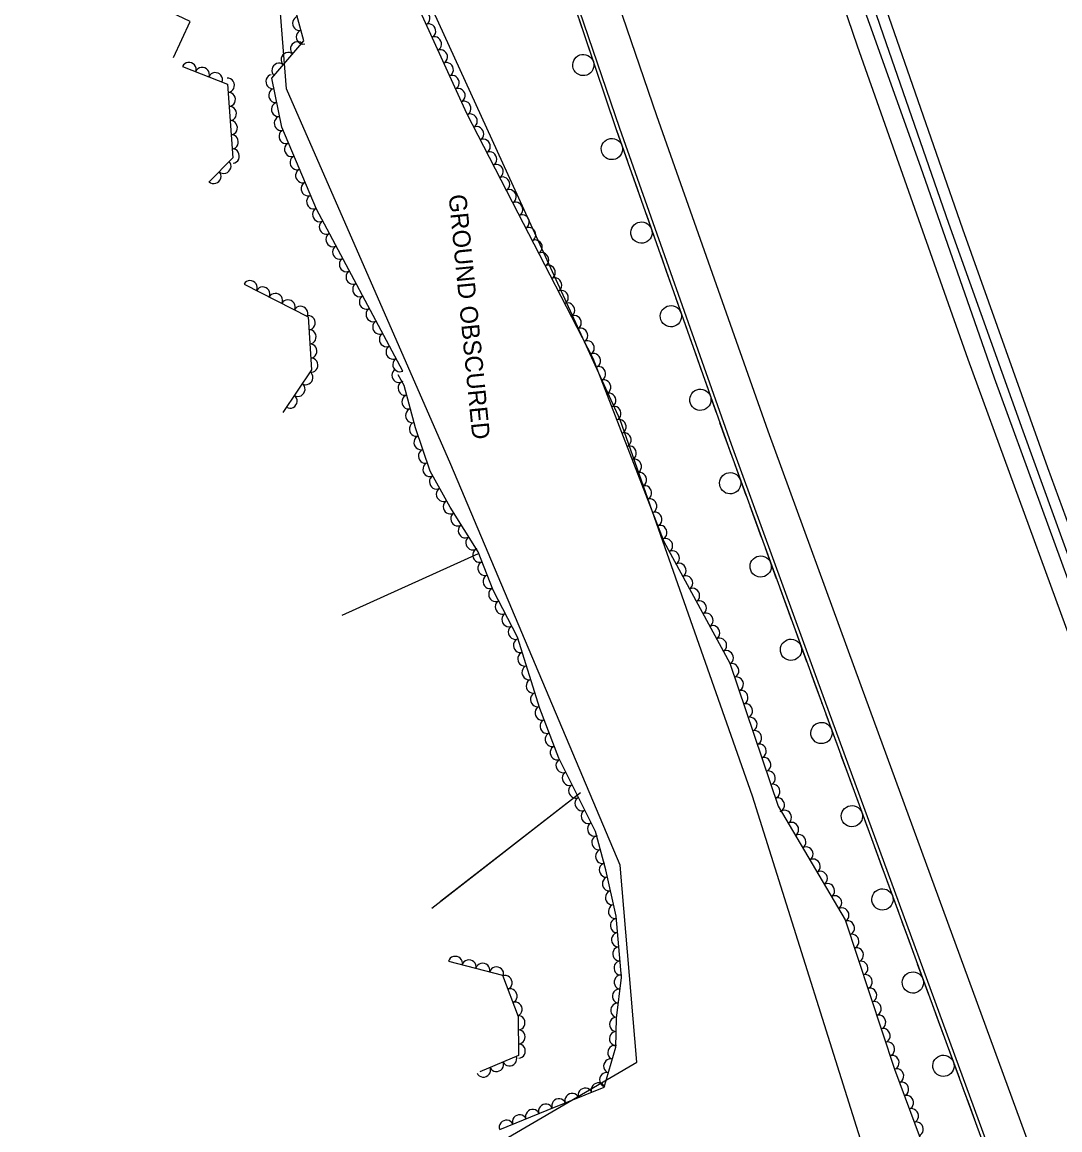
# Model space of a CAD drawing. Extents: x 1746719 to 1766531, y 631721 to 662391.
# Drawn here: x 1754164.2 to 1754457, y 649456.3 to 649768.8 of the extents above; entities that cross this region are included whole.
import ezdxf

# ---------------------------------------------------------------- set-up
doc = ezdxf.new("R2010")
doc.units = 0
for name, color, linetype in [('SURVEY - AERIAL SURVEY - Photo Control - Points - Elevations', 7, 'Continuous'), ('SURVEY - AERIAL SURVEY - Photo Control - Points - Locators', 7, 'Continuous'), ('SURVEY - AERIAL SURVEY - Photo Control - Points - Numbers', 7, 'Continuous'), ('SURVEY - AERIAL SURVEY - Photo Control with Text', 7, 'Continuous'), ('SURVEY - CENTERLINE - Existing Roads Curve Text', 7, 'Continuous')]:
    doc.layers.add(name, color=color, linetype=linetype)

msp = doc.modelspace()

# ---------------------------------------------------------------- linework, layer by layer
at = {"layer": 'SURVEY - AERIAL SURVEY - Photo Control - Points - Elevations'}
for points in [[(1754298.66, 649872.79), (1754343.18, 649742.47), (1754374.58, 649653.49), (1754400.82, 649581.61), (1754453.23, 649438.62)], [(1754289.89, 649864.41), (1754332.79, 649738.86), (1754364.23, 649649.77), (1754390.49, 649577.83), (1754442.91, 649434.83)], [(1754372.91, 649841.05), (1754399.86, 649762.15), (1754431.05, 649673.76), (1754457.17, 649602.22), (1754509.57, 649459.27)], [(1754519.88, 649459.84), (1754496.93, 649522.97), (1754475.36, 649583.78), (1754453.6, 649643.04), (1754429.6, 649710.4), (1754402.92, 649787.27), (1754386.52, 649835.23)]]:
    msp.add_lwpolyline(points, dxfattribs=at)
at = {"layer": 'SURVEY - AERIAL SURVEY - Photo Control - Points - Locators'}
msp.add_lwpolyline([(1754306.65, 649427.15), (1754301.44, 649454.25), (1754337.64, 649475.34), (1754332.91, 649530.99), (1754285.2, 649644.02), (1754238.76, 649749.99), (1754236.2, 649783.3), (1754205.23, 649865.29), (1754178.89, 649843.08), (1754164.2, 649889.48), (1754197.11, 649948.37), (1754220.8, 649913.17), (1754277.14, 649778.61), (1754332.9, 649656.66), (1754370.16, 649550.51), (1754404.93, 649440.26), (1754306.65, 649427.15)], dxfattribs=at)
at = {"layer": 'SURVEY - AERIAL SURVEY - Photo Control - Points - Numbers'}
for points in [[(1754289.46, 649864.22), (1754331.85, 649738.54), (1754363.29, 649649.43), (1754389.55, 649577.48), (1754441.97, 649434.49)], [(1754379.58, 649838.2), (1754396.39, 649787.83), (1754417.71, 649728.02), (1754438.48, 649668.45), (1754465.02, 649595.86), (1754484.29, 649542.97), (1754514.24, 649459.31)], [(1754516.62, 649459.65), (1754501.04, 649503.67), (1754483.8, 649551.83), (1754466.56, 649598.63), (1754446.68, 649653.43), (1754425.68, 649712.01), (1754407.27, 649765.12), (1754389.44, 649816.85), (1754382.87, 649836.79)], [(1754321.42, 649769.46), (1754322.92, 649765.01)], [(1754323.94, 649761.98), (1754326.88, 649753.26)], [(1754327.9, 649750.23), (1754329.41, 649745.77)], [(1754329.41, 649745.77), (1754330.91, 649741.32)], [(1754331.93, 649738.29), (1754335, 649729.61)], [(1754336.06, 649726.59), (1754337.62, 649722.16)], [(1754337.62, 649722.16), (1754339.19, 649717.73)], [(1754340.25, 649714.71), (1754343.31, 649706.04)], [(1754344.38, 649703.02), (1754345.94, 649698.59)], [(1754345.94, 649698.59), (1754347.51, 649694.16)], [(1754348.57, 649691.14), (1754351.63, 649682.46)], [(1754352.7, 649679.44), (1754354.26, 649675.01)], [(1754354.26, 649675.01), (1754355.82, 649670.58)], [(1754356.89, 649667.56), (1754359.95, 649658.89)], [(1754361.02, 649655.87), (1754362.58, 649651.44)], [(1754362.58, 649651.44), (1754363.29, 649649.43), (1754364.17, 649647.01)], [(1754365.27, 649644.01), (1754368.42, 649635.37)], [(1754369.52, 649632.36), (1754371.13, 649627.95)], [(1754371.13, 649627.95), (1754372.74, 649623.53)], [(1754373.84, 649620.52), (1754377, 649611.88)], [(1754378.09, 649608.88), (1754379.71, 649604.46)], [(1754379.71, 649604.46), (1754381.32, 649600.05)], [(1754382.42, 649597.04), (1754385.57, 649588.4)], [(1754386.67, 649585.39), (1754388.28, 649580.98)], [(1754388.28, 649580.98), (1754389.55, 649577.48), (1754389.89, 649576.56)], [(1754390.99, 649573.56), (1754394.16, 649564.92)], [(1754395.26, 649561.92), (1754396.88, 649557.5)], [(1754396.88, 649557.5), (1754398.5, 649553.09)], [(1754399.6, 649550.08), (1754402.76, 649541.45)], [(1754403.86, 649538.44), (1754405.48, 649534.03)], [(1754405.48, 649534.03), (1754407.1, 649529.62)], [(1754408.2, 649526.61), (1754411.37, 649517.97)], [(1754412.47, 649514.97), (1754414.09, 649510.56)], [(1754414.09, 649510.56), (1754415.7, 649506.14)], [(1754416.8, 649503.14), (1754419.97, 649494.5)], [(1754421.07, 649491.5), (1754422.69, 649487.08)], [(1754422.69, 649487.08), (1754424.31, 649482.67)], [(1754425.41, 649479.67), (1754428.57, 649471.03)], [(1754429.68, 649468.02), (1754431.29, 649463.61)], [(1754431.29, 649463.61), (1754432.91, 649459.2)]]:
    msp.add_lwpolyline(points, dxfattribs=at)
for centre, start, end in [((1754322.55, 649756.7), 131.9077, 131.8937), ((1754330.62, 649733), 132.7034, 132.6894), ((1754338.94, 649709.42), 132.7034, 132.6894), ((1754347.26, 649685.84), 132.7034, 132.6894), ((1754355.58, 649662.27), 132.7034, 132.6894), ((1754364.01, 649638.7), 133.3255, 133.3115), ((1754372.59, 649615.22), 133.3255, 133.3115), ((1754381.16, 649591.73), 133.3255, 133.3115), ((1754389.74, 649568.25), 133.3982, 133.3842), ((1754398.35, 649544.78), 133.3982, 133.3842), ((1754406.95, 649521.3), 133.3982, 133.3842), ((1754415.56, 649497.83), 133.3982, 133.3842), ((1754424.16, 649474.36), 133.3982, 133.3842)]:
    msp.add_arc(centre, 3, start, end, dxfattribs=at)
at = {"layer": 'SURVEY - AERIAL SURVEY - Photo Control with Text'}
for points in [[(1754166.74, 649890.48), (1754176.87, 649920.51), (1754184.32, 649931.68), (1754190.2, 649940.32), (1754197.86, 649945.85), (1754217.64, 649930.63), (1754230.89, 649883.58), (1754250.56, 649822.66), (1754267.73, 649791.06), (1754289.59, 649743.11), (1754304.09, 649714.97), (1754325.28, 649673.97), (1754345.25, 649622.29), (1754363.86, 649587.9), (1754377.55, 649547.63), (1754396.42, 649515.54), (1754410.38, 649473.41), (1754419.07, 649449.85)], [(1754271.62, 649670.36), (1754247.23, 649716.04), (1754237.44, 649739.16), (1754234.66, 649753.04), (1754243.71, 649763.54), (1754236.47, 649790.24), (1754224.48, 649823.51), (1754211.15, 649858.52), (1754204.97, 649870.03), (1754198.07, 649874.53), (1754190, 649863.67), (1754179.33, 649845.57)], [(1754209.47, 649756.3), (1754222.19, 649751.34), (1754223.64, 649730.51), (1754216.86, 649723.64)], [(1754226.81, 649694.9), (1754244.89, 649685.69), (1754245.85, 649670.72), (1754237.79, 649658.7)], [(1754298.95, 649456.36), (1754312.36, 649461.84), (1754328.4, 649468.32), (1754331.77, 649479.58), (1754331.87, 649487.77), (1754333.31, 649499.29), (1754331.81, 649516.59), (1754328.92, 649529.61), (1754325.95, 649540.49), (1754315.67, 649561.15), (1754310.32, 649575.14), (1754303.98, 649595.32), (1754297.09, 649608.55), (1754292.85, 649619.39), (1754284.95, 649631.96), (1754279.35, 649642.09), (1754275.23, 649654.34), (1754271.97, 649666.27), (1754270.33, 649669.26)], [(1754284.51, 649503.83), (1754299.76, 649499.96), (1754304.19, 649488.27), (1754304.3, 649477.24), (1754293.35, 649472.61)]]:
    msp.add_lwpolyline(points, dxfattribs=at)
for centre, major_axis in [((1754277.34, 649769.98), (0.83, -1.82)), ((1754242.38, 649768.45), (-0.52, 1.93)), ((1754279, 649766.34), (0.83, -1.82)), ((1754243.42, 649764.59), (-0.52, 1.93)), ((1754280.66, 649762.7), (0.83, -1.82)), ((1754241.82, 649761.34), (1.31, 1.51)), ((1754282.32, 649759.06), (0.83, -1.82)), ((1754239.2, 649758.31), (1.31, 1.51)), ((1754211.33, 649755.57), (1.86, -0.73)), ((1754215.06, 649754.12), (1.86, -0.73)), ((1754236.59, 649755.28), (1.31, 1.51)), ((1754283.98, 649755.43), (0.83, -1.82)), ((1754218.78, 649752.67), (1.86, -0.73)), ((1754222.21, 649750.99), (0.14, -2)), ((1754234.87, 649752.02), (-0.39, 1.96)), ((1754285.64, 649751.79), (0.83, -1.82)), ((1754222.49, 649747), (0.14, -2)), ((1754235.65, 649748.1), (-0.39, 1.96)), ((1754287.3, 649748.15), (0.83, -1.82)), ((1754236.44, 649744.17), (-0.39, 1.96)), ((1754288.95, 649744.51), (0.83, -1.82)), ((1754222.77, 649743.01), (0.14, -2)), ((1754290.72, 649740.92), (0.92, -1.78)), ((1754223.04, 649739.02), (0.14, -2)), ((1754237.22, 649740.25), (-0.39, 1.96)), ((1754292.55, 649737.36), (0.92, -1.78)), ((1754223.32, 649735.03), (0.14, -2)), ((1754238.57, 649736.5), (-0.78, 1.84)), ((1754223.6, 649731.04), (0.14, -2)), ((1754240.13, 649732.82), (-0.78, 1.84)), ((1754294.39, 649733.81), (0.92, -1.78)), ((1754241.69, 649729.13), (-0.78, 1.84)), ((1754296.22, 649730.25), (0.92, -1.78)), ((1754221.2, 649728.04), (-1.4, -1.42)), ((1754243.25, 649725.45), (-0.78, 1.84)), ((1754298.05, 649726.7), (0.92, -1.78)), ((1754218.39, 649725.2), (-1.4, -1.42)), ((1754299.88, 649723.14), (0.92, -1.78)), ((1754244.81, 649721.77), (-0.78, 1.84)), ((1754301.71, 649719.58), (0.92, -1.78)), ((1754246.37, 649718.08), (-0.78, 1.84)), ((1754303.55, 649716.03), (0.92, -1.78)), ((1754248.07, 649714.47), (-0.94, 1.76)), ((1754305.38, 649712.47), (0.92, -1.78)), ((1754249.95, 649710.94), (-0.94, 1.76)), ((1754251.84, 649707.41), (-0.94, 1.76)), ((1754307.22, 649708.92), (0.92, -1.78)), ((1754253.72, 649703.88), (-0.94, 1.76)), ((1754309.05, 649705.37), (0.92, -1.78)), ((1754255.61, 649700.36), (-0.94, 1.76)), ((1754310.89, 649701.81), (0.92, -1.78)), ((1754312.73, 649698.26), (0.92, -1.78)), ((1754228.59, 649693.99), (1.78, -0.91)), ((1754257.49, 649696.83), (-0.94, 1.76)), ((1754314.56, 649694.71), (0.92, -1.78)), ((1754232.16, 649692.18), (1.78, -0.91)), ((1754235.72, 649690.36), (1.78, -0.91)), ((1754259.37, 649693.3), (-0.94, 1.76)), ((1754316.4, 649691.15), (0.92, -1.78)), ((1754239.29, 649688.55), (1.78, -0.91)), ((1754261.26, 649689.77), (-0.94, 1.76)), ((1754318.23, 649687.6), (0.92, -1.78)), ((1754242.85, 649686.73), (1.78, -0.91)), ((1754263.14, 649686.24), (-0.94, 1.76)), ((1754320.07, 649684.04), (0.92, -1.78)), ((1754245, 649683.99), (0.13, -2)), ((1754265.03, 649682.71), (-0.94, 1.76)), ((1754245.26, 649680), (0.13, -2)), ((1754266.91, 649679.18), (-0.94, 1.76)), ((1754321.91, 649680.49), (0.92, -1.78)), ((1754245.51, 649676), (0.13, -2)), ((1754268.79, 649675.66), (-0.94, 1.76)), ((1754323.74, 649676.94), (0.92, -1.78)), ((1754245.76, 649672.01), (0.13, -2)), ((1754270.68, 649672.13), (-0.94, 1.76)), ((1754325.51, 649673.35), (0.72, -1.87)), ((1754270.43, 649669.08), (-0.96, 1.75)), ((1754326.95, 649669.62), (0.72, -1.87)), ((1754244.34, 649668.47), (-1.11, -1.66)), ((1754328.4, 649665.89), (0.72, -1.87)), ((1754242.11, 649665.15), (-1.11, -1.66)), ((1754272.17, 649665.51), (-0.53, 1.93)), ((1754329.84, 649662.16), (0.72, -1.87)), ((1754239.89, 649661.83), (-1.11, -1.66)), ((1754273.23, 649661.65), (-0.53, 1.93)), ((1754274.28, 649657.79), (-0.53, 1.93)), ((1754331.28, 649658.43), (0.72, -1.87)), ((1754275.36, 649653.94), (-0.64, 1.9)), ((1754332.72, 649654.7), (0.72, -1.87)), ((1754276.64, 649650.15), (-0.64, 1.9)), ((1754334.16, 649650.97), (0.72, -1.87)), ((1754335.61, 649647.24), (0.72, -1.87)), ((1754277.92, 649646.36), (-0.64, 1.9)), ((1754337.05, 649643.51), (0.72, -1.87)), ((1754279.19, 649642.57), (-0.64, 1.9)), ((1754281.04, 649639.03), (-0.97, 1.75)), ((1754338.49, 649639.77), (0.72, -1.87)), ((1754282.98, 649635.53), (-0.97, 1.75)), ((1754339.93, 649636.04), (0.72, -1.87)), ((1754284.91, 649632.02), (-0.97, 1.75)), ((1754341.37, 649632.31), (0.72, -1.87)), ((1754287.03, 649628.63), (-1.06, 1.69)), ((1754342.82, 649628.58), (0.72, -1.87)), ((1754289.16, 649625.25), (-1.06, 1.69)), ((1754344.26, 649624.85), (0.72, -1.87)), ((1754291.29, 649621.86), (-1.06, 1.69)), ((1754345.84, 649621.19), (0.95, -1.76)), ((1754293.24, 649618.38), (-0.73, 1.86)), ((1754347.75, 649617.67), (0.95, -1.76)), ((1754294.7, 649614.66), (-0.73, 1.86)), ((1754349.65, 649614.15), (0.95, -1.76)), ((1754296.16, 649610.94), (-0.73, 1.86)), ((1754351.56, 649610.63), (0.95, -1.76)), ((1754297.75, 649607.27), (-0.92, 1.77)), ((1754353.46, 649607.11), (0.95, -1.76)), ((1754299.6, 649603.73), (-0.92, 1.77)), ((1754355.36, 649603.6), (0.95, -1.76)), ((1754301.45, 649600.18), (-0.92, 1.77)), ((1754357.27, 649600.08), (0.95, -1.76)), ((1754359.17, 649596.56), (0.95, -1.76)), ((1754303.29, 649596.63), (-0.92, 1.77)), ((1754304.73, 649592.91), (-0.6, 1.91)), ((1754361.07, 649593.04), (0.95, -1.76)), ((1754305.93, 649589.1), (-0.6, 1.91)), ((1754362.98, 649589.53), (0.95, -1.76)), ((1754307.13, 649585.28), (-0.6, 1.91)), ((1754364.55, 649585.86), (0.64, -1.89)), ((1754308.33, 649581.47), (-0.6, 1.91)), ((1754365.84, 649582.08), (0.64, -1.89)), ((1754367.13, 649578.29), (0.64, -1.89)), ((1754309.53, 649577.65), (-0.6, 1.91)), ((1754310.81, 649573.86), (-0.71, 1.87)), ((1754368.41, 649574.5), (0.64, -1.89)), ((1754312.24, 649570.12), (-0.71, 1.87)), ((1754369.7, 649570.71), (0.64, -1.89)), ((1754313.67, 649566.39), (-0.71, 1.87)), ((1754370.99, 649566.93), (0.64, -1.89)), ((1754315.1, 649562.65), (-0.71, 1.87)), ((1754372.28, 649563.14), (0.64, -1.89)), ((1754373.56, 649559.35), (0.64, -1.89)), ((1754316.74, 649559.01), (-0.89, 1.79)), ((1754318.52, 649555.43), (-0.89, 1.79)), ((1754374.85, 649555.57), (0.64, -1.89)), ((1754320.3, 649551.85), (-0.89, 1.79)), ((1754376.14, 649551.78), (0.64, -1.89)), ((1754322.08, 649548.26), (-0.89, 1.79)), ((1754377.43, 649547.99), (0.64, -1.89)), ((1754323.86, 649544.68), (-0.89, 1.79)), ((1754379.39, 649544.51), (1.01, -1.72)), ((1754325.64, 649541.1), (-0.89, 1.79)), ((1754381.41, 649541.06), (1.01, -1.72)), ((1754383.44, 649537.62), (1.01, -1.72)), ((1754326.82, 649537.29), (-0.53, 1.93)), ((1754385.47, 649534.17), (1.01, -1.72)), ((1754327.88, 649533.43), (-0.53, 1.93)), ((1754328.93, 649529.57), (-0.43, 1.95)), ((1754387.5, 649530.72), (1.01, -1.72)), ((1754329.8, 649525.67), (-0.43, 1.95)), ((1754389.52, 649527.27), (1.01, -1.72)), ((1754391.55, 649523.82), (1.01, -1.72)), ((1754330.66, 649521.76), (-0.43, 1.95)), ((1754393.58, 649520.38), (1.01, -1.72)), ((1754331.53, 649517.86), (-0.43, 1.95)), ((1754395.61, 649516.93), (1.01, -1.72)), ((1754332.05, 649513.9), (-0.17, 1.99)), ((1754397.17, 649513.27), (0.63, -1.9)), ((1754332.39, 649509.91), (-0.17, 1.99)), ((1754398.43, 649509.47), (0.63, -1.9)), ((1754286.45, 649503.34), (1.94, -0.49)), ((1754332.73, 649505.93), (-0.17, 1.99)), ((1754399.69, 649505.68), (0.63, -1.9)), ((1754290.32, 649502.35), (1.94, -0.49)), ((1754294.2, 649501.37), (1.94, -0.49)), ((1754298.08, 649500.39), (1.94, -0.49)), ((1754333.08, 649501.94), (-0.17, 1.99)), ((1754400.95, 649501.88), (0.63, -1.9)), ((1754300.56, 649497.84), (0.71, -1.87)), ((1754333.14, 649497.96), (0.25, 1.98)), ((1754402.2, 649498.08), (0.63, -1.9)), ((1754301.98, 649494.1), (0.71, -1.87)), ((1754332.65, 649493.99), (0.25, 1.98)), ((1754403.46, 649494.29), (0.63, -1.9)), ((1754303.4, 649490.36), (0.71, -1.87)), ((1754404.72, 649490.49), (0.63, -1.9)), ((1754332.15, 649490.02), (0.25, 1.98)), ((1754304.21, 649486.51), (0.02, -2)), ((1754331.85, 649486.04), (0.02, 2)), ((1754405.98, 649486.69), (0.63, -1.9)), ((1754304.25, 649482.51), (0.02, -2)), ((1754331.8, 649482.04), (0.02, 2)), ((1754407.24, 649482.89), (0.63, -1.9)), ((1754304.29, 649478.51), (0.02, -2)), ((1754331.33, 649478.11), (0.57, 1.92)), ((1754408.5, 649479.1), (0.63, -1.9)), ((1754301.78, 649476.18), (-1.84, -0.78)), ((1754409.75, 649475.3), (0.63, -1.9)), ((1754294.41, 649473.06), (-1.84, -0.78)), ((1754298.09, 649474.62), (-1.84, -0.78)), ((1754330.18, 649474.28), (0.57, 1.92)), ((1754411.07, 649471.53), (0.69, -1.88)), ((1754329.03, 649470.44), (0.57, 1.92)), ((1754323.04, 649466.15), (1.85, 0.75)), ((1754326.75, 649467.65), (1.85, 0.75)), ((1754412.46, 649467.77), (0.69, -1.88)), ((1754315.62, 649463.16), (1.85, 0.75)), ((1754319.33, 649464.66), (1.85, 0.75)), ((1754413.84, 649464.02), (0.69, -1.88)), ((1754308.21, 649460.15), (1.85, 0.76)), ((1754311.91, 649461.66), (1.85, 0.76)), ((1754415.23, 649460.27), (0.69, -1.88)), ((1754300.8, 649457.12), (1.85, 0.76)), ((1754304.51, 649458.63), (1.85, 0.76)), ((1754416.61, 649456.51), (0.69, -1.88))]:
    msp.add_ellipse(centre, major_axis=major_axis, ratio=0.940188, start_param=0, end_param=3.141593, dxfattribs=at)
at = {"layer": 'SURVEY - CENTERLINE - Existing Roads Curve Text'}
for points in [[(1754206.92, 649758.86), (1754211.57, 649769.02), (1754202.89, 649773.12), (1754208.48, 649786.11), (1754200.22, 649789.01)], [(1754292.89, 649618.75), (1754254.45, 649601.42)], [(1754292.89, 649618.75), (1754254.45, 649601.42)], [(1754321.76, 649551.37), (1754279.77, 649518.76)], [(1754321.76, 649551.37), (1754282.27, 649520.7)]]:
    msp.add_lwpolyline(points, dxfattribs=at)

# ---------------------------------------------------------------- texts
at = {"layer": 'SURVEY - AERIAL SURVEY - Photo Control - Points - Locators'}
msp.add_text('GROUND OBSCURED', height=5, rotation=275.6107, dxfattribs=at).set_placement((1754284.52, 649719.99))

doc.saveas('drawing.dxf')
